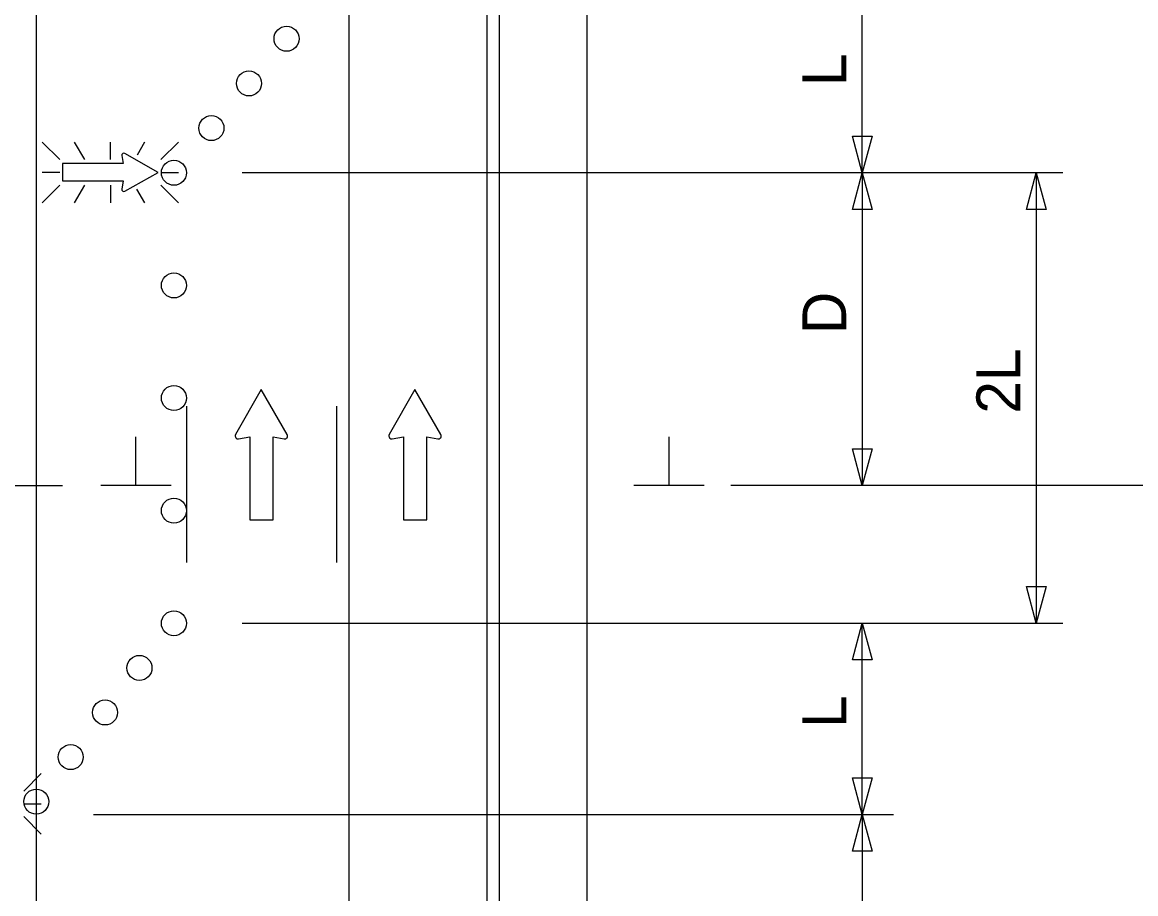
# Model space of a CAD drawing. Extents: x 16782 to 19504, y 6935 to 8243.
# Drawn here: x 17980.9 to 18158.8, y 7755.7 to 7895 of the extents above; entities that cross this region are included whole.
import ezdxf

# ---------------------------------------------------------------- set-up
doc = ezdxf.new("R2010")
doc.units = 0
for name, color, linetype in [('ALI_LEGAL_EX', 7, 'Continuous'), ('MT_SCRATCH_LEVEL_E', 7, 'Continuous'), ('PAVT_EDGE_EX', 7, 'Continuous'), ('TRAFFIC_SIGNS_PR', 7, 'Continuous'), ('TYPICAL_TEXT_DIMEN_PR', 7, 'Continuous')]:
    doc.layers.add(name, color=color, linetype=linetype)

msp = doc.modelspace()

# ---------------------------------------------------------------- linework, layer by layer
at = {"layer": 'ALI_LEGAL_EX'}
for p, q in [((18033.11, 8234.45), (18033.11, 7405.27)), ((18057.11, 8234.45), (18057.11, 7405.27)), ((18057.11, 8234.45), (18057.11, 7405.27))]:
    msp.add_line(p, q, dxfattribs=at)
for points in [[(18007.13, 7833.65), (18007.13, 7808.65)], [(18031.13, 7833.65), (18031.13, 7808.65)]]:
    msp.add_lwpolyline(points, dxfattribs=at)
at = {"layer": 'MT_SCRATCH_LEVEL_E'}
for p, q in [((18019.1, 7836.32), (18014.98, 7829.08)), ((18023.24, 7829.08), (18019.1, 7836.32)), ((18043.65, 7836.32), (18039.54, 7829.08)), ((18047.8, 7829.08), (18043.65, 7836.32)), ((18015.47, 7828.4), (18017.24, 7828.71)), ((18017.24, 7828.71), (18017.24, 7815.45)), ((18020.99, 7815.45), (18020.99, 7828.71)), ((18020.99, 7828.71), (18022.76, 7828.4)), ((18040.03, 7828.4), (18041.8, 7828.71)), ((18041.8, 7828.71), (18041.8, 7815.45)), ((18045.54, 7815.45), (18045.54, 7828.71)), ((18045.54, 7828.71), (18047.32, 7828.4)), ((18017.24, 7815.45), (18020.99, 7815.45)), ((18041.8, 7815.45), (18045.54, 7815.45))]:
    msp.add_line(p, q, dxfattribs=at)
for centre, start, end in [((18015.39, 7828.86), 150.4248, 279.9638), ((18022.83, 7828.86), 260.0362, 29.7731), ((18039.95, 7828.86), 150.4248, 279.9638), ((18047.39, 7828.86), 260.0362, 29.7731)]:
    msp.add_arc(centre, 0.463, start, end, dxfattribs=at)
at = {"layer": 'PAVT_EDGE_EX'}
for p, q in [((17983.13, 8183.26), (17983.13, 7404.46)), ((18055.13, 8183.26), (18055.13, 7404.46)), ((18071.13, 8183.26), (18071.13, 7404.46))]:
    msp.add_line(p, q, dxfattribs=at)
at = {"layer": 'TRAFFIC_SIGNS_PR'}
for p, q in [((17986.9, 7873.03), (17984.08, 7875.85)), ((17989.2, 7875.85), (17990.83, 7873.03)), ((17994.99, 7873.03), (17994.99, 7875.85)), ((18000.46, 7875.85), (17999.25, 7873.76)), ((18005.89, 7875.85), (18003.07, 7873.03)), ((17986.9, 7871), (17984.08, 7871)), ((18003.07, 7871), (18005.89, 7871)), ((17986.9, 7868.97), (17984.08, 7866.15)), ((17990.85, 7868.97), (17989.22, 7866.15)), ((17994.99, 7868.97), (17994.99, 7866.15)), ((17999.17, 7868.33), (18000.43, 7866.15)), ((18005.89, 7866.15), (18003.07, 7868.97)), ((17983.94, 7774.93), (17981.13, 7772.11)), ((17981.13, 7770.08), (17983.94, 7770.08)), ((17983.94, 7765.23), (17981.13, 7768.04))]:
    msp.add_line(p, q, dxfattribs=at)
for points in [[(17996.81, 7873.68), (17997.04, 7872.39), (17987.32, 7872.39), (17987.32, 7869.64), (17997.04, 7869.64), (17996.81, 7868.34)], [(17997.31, 7867.99), (18002.62, 7871), (17997.31, 7874.04)]]:
    msp.add_lwpolyline(points, dxfattribs=at)
for centre in [(18023.13, 7892.35), (18017.13, 7885.21), (18011.13, 7878.07), (18005.13, 7870.93), (18005.13, 7852.93), (18005.13, 7834.93), (18005.13, 7816.93), (18005.13, 7798.93), (17999.63, 7791.8), (17994.13, 7784.67), (17988.64, 7777.54), (17983.14, 7770.42)]:
    msp.add_circle(centre, 2, dxfattribs=at)
for centre, start, end in [((17997.15, 7873.74), 61.4833, 189.9593), ((17997.15, 7868.28), 170.7308, 298.8916)]:
    msp.add_arc(centre, 0.341, start, end, dxfattribs=at)
at = {"layer": 'TYPICAL_TEXT_DIMEN_PR'}
for p, q in [((18115.13, 7870.93), (18115.13, 7901.49)), ((18115.13, 7870.93), (18113.56, 7876.79)), ((18113.56, 7876.79), (18115.13, 7876.79)), ((18115.13, 7876.79), (18116.7, 7876.79)), ((18116.7, 7876.79), (18115.13, 7870.93)), ((18147.17, 7870.93), (18016.03, 7870.93)), ((18113.56, 7865.07), (18115.13, 7870.93)), ((18115.13, 7870.93), (18115.13, 7820.93)), ((18115.13, 7870.93), (18116.7, 7865.07)), ((18141.36, 7865.07), (18142.93, 7870.93)), ((18142.93, 7870.93), (18144.5, 7865.07)), ((18142.93, 7870.93), (18142.93, 7798.93)), ((18115.13, 7865.07), (18113.56, 7865.07)), ((18116.7, 7865.07), (18115.13, 7865.07)), ((18142.93, 7865.07), (18141.36, 7865.07)), ((18144.5, 7865.07), (18142.93, 7865.07)), ((17999.05, 7820.93), (17999.05, 7828.71)), ((18084.25, 7820.93), (18084.25, 7828.71)), ((18115.13, 7820.93), (18113.56, 7826.79)), ((18113.56, 7826.79), (18115.13, 7826.79)), ((18115.13, 7826.79), (18116.7, 7826.79)), ((18116.7, 7826.79), (18115.13, 7820.93)), ((18142.93, 7825.8), (18142.93, 7822.03)), ((17905.13, 7820.93), (17987.32, 7820.93)), ((18004.68, 7820.93), (17993.43, 7820.93)), ((18089.88, 7820.93), (18078.63, 7820.93)), ((18196.62, 7820.93), (18094.13, 7820.93)), ((18142.93, 7798.93), (18141.36, 7804.79)), ((18141.36, 7804.79), (18142.93, 7804.79)), ((18142.93, 7804.79), (18144.5, 7804.79)), ((18144.5, 7804.79), (18142.93, 7798.93)), ((18016.03, 7798.93), (18147.17, 7798.93)), ((18113.56, 7793.07), (18115.13, 7798.93)), ((18115.13, 7768.36), (18115.13, 7798.93)), ((18115.13, 7798.93), (18116.7, 7793.07)), ((18115.13, 7793.07), (18113.56, 7793.07)), ((18116.7, 7793.07), (18115.13, 7793.07)), ((18115.13, 7768.36), (18113.56, 7774.23)), ((18113.56, 7774.23), (18115.13, 7774.23)), ((18115.13, 7774.23), (18116.7, 7774.23)), ((18116.7, 7774.23), (18115.13, 7768.36)), ((17992.29, 7768.36), (18120.13, 7768.36)), ((18113.56, 7762.5), (18115.13, 7768.36)), ((18115.13, 7768.36), (18115.13, 7718.36)), ((18115.13, 7768.36), (18116.7, 7762.5)), ((18115.13, 7762.5), (18113.56, 7762.5)), ((18116.7, 7762.5), (18115.13, 7762.5))]:
    msp.add_line(p, q, dxfattribs=at)

# ---------------------------------------------------------------- texts
for s, p in [('L', (18112.57, 7884.79)), ('D', (18112.57, 7845.15)), ('2L', (18140.37, 7832.43)), ('L', (18112.57, 7782.22))]:
    msp.add_text(s, height=7, rotation=90, dxfattribs=at).set_placement(p)

doc.saveas('drawing.dxf')
